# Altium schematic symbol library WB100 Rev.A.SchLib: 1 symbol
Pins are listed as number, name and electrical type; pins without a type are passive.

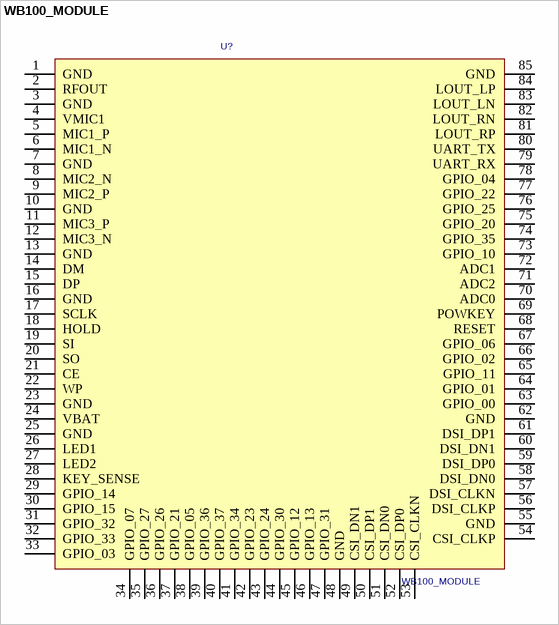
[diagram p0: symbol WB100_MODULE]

## WB100_MODULE
designator U?
PCB DECAL: MODULE-85P-FSP
footprint MODULE-85P-FSP
pins: 1 GND, 2 RFOUT, 3 GND, 4 VMIC1, 5 MIC1_P, 6 MIC1_N, 7 GND, 8 MIC2_N, 9 MIC2_P, 10 GND, 11 MIC3_P, 12 MIC3_N, 13 GND, 14 DM, 15 DP, 16 GND, 17 SCLK, 18 HOLD, 19 SI, 20 SO, 21 CE, 22 WP, 23 GND, 24 VBAT, 25 GND, 26 LED1, 27 LED2, 28 KEY_SENSE, 29 GPIO_14, 30 GPIO_15, 31 GPIO_32, 32 GPIO_33, 33 GPIO_03, 34 GPIO_07, 35 GPIO_27, 36 GPIO_26, 37 GPIO_21, 38 GPIO_05, 39 GPIO_36, 40 GPIO_37, 41 GPIO_34, 42 GPIO_23, 43 GPIO_24, 44 GPIO_30, 45 GPIO_12, 46 GPIO_13, 47 GPIO_31, 48 GND, 49 CSI_DN1, 50 CSI_DP1, 51 CSI_DN0, 52 CSI_DP0, 53 CSI_CLKN, 54 CSI_CLKP, 55 GND, 56 DSI_CLKP, 57 DSI_CLKN, 58 DSI_DN0, 59 DSI_DP0, 60 DSI_DN1, 61 DSI_DP1, 62 GND, 63 GPIO_00, 64 GPIO_01, 65 GPIO_11, 66 GPIO_02, 67 GPIO_06, 68 RESET, 69 POWKEY, 70 ADC0, 71 ADC2, 72 ADC1, 73 GPIO_10, 74 GPIO_35, 75 GPIO_20, 76 GPIO_25, 77 GPIO_22, 78 GPIO_04, 79 UART_RX, 80 UART_TX, 81 LOUT_RP, 82 LOUT_RN, 83 LOUT_LN, 84 LOUT_LP, 85 GND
